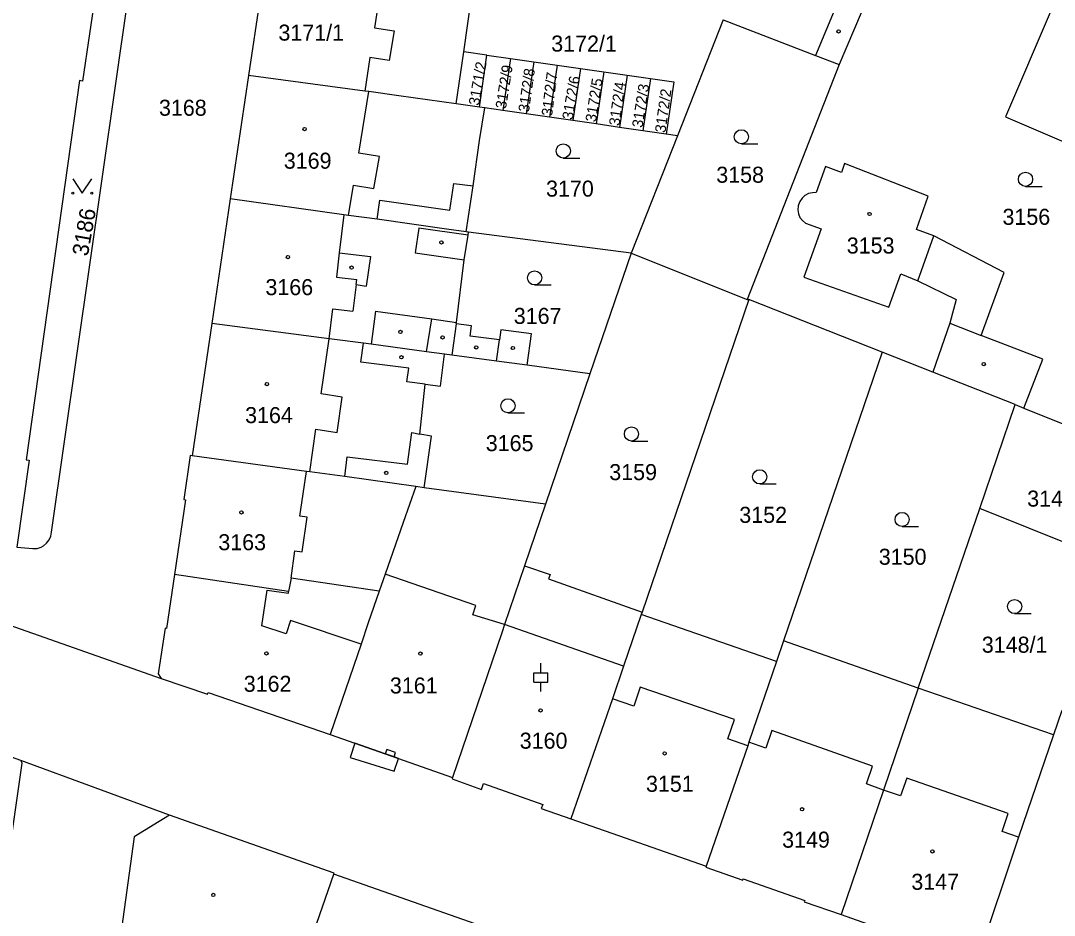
# Model space of a CAD drawing. Extents: x -756746 to -753363, y -1166406 to -1161727.
# Drawn here: x -755498.1 to -755388.6, y -1165398.7 to -1165303.9 of the extents above; entities that cross this region are included whole.
import ezdxf

# ---------------------------------------------------------------- set-up
doc = ezdxf.new("R2010")
doc.units = 0
for name, color, linetype in [('Hranice parcel', 7, 'Continuous'), ('Parcelní čísla', 7, 'Continuous'), ('Vnitřní kresba', 7, 'Continuous'), ('Věcná břemena k části', 7, 'Continuous'), ('Značky budov', 7, 'Continuous'), ('Značky kultur', 7, 'Continuous')]:
    doc.layers.add(name, color=color, linetype=linetype)

msp = doc.modelspace()

# ---------------------------------------------------------------- linework, layer by layer
at = {"layer": 'Hranice parcel'}
for p, q in [((-755471.99, -1165296.5), (-755474, -1165309.75)), ((-755451.19, -1165307.22), (-755450.11, -1165299.59)), ((-755494.86, -1165358.12), (-755486.67, -1165300.84)), ((-755423.7, -1165303.84), (-755428.53, -1165316.11)), ((-755451.98, -1165312.75), (-755451.19, -1165307.22)), ((-755448.72, -1165307.57), (-755451.19, -1165307.22)), ((-755449.5, -1165313.09), (-755448.72, -1165307.57)), ((-755448.72, -1165307.57), (-755446.24, -1165307.93)), ((-755446.24, -1165307.93), (-755447.03, -1165313.45)), ((-755446.24, -1165307.93), (-755443.77, -1165308.28)), ((-755443.77, -1165308.28), (-755444.56, -1165313.8)), ((-755443.77, -1165308.28), (-755441.29, -1165308.63)), ((-755441.29, -1165308.63), (-755442.08, -1165314.16)), ((-755441.29, -1165308.63), (-755438.82, -1165308.99)), ((-755438.82, -1165308.99), (-755439.61, -1165314.51)), ((-755438.82, -1165308.99), (-755436.35, -1165309.34)), ((-755436.35, -1165309.34), (-755437.14, -1165314.87)), ((-755436.35, -1165309.34), (-755433.87, -1165309.69)), ((-755411.4, -1165308.58), (-755421.15, -1165333.47)), ((-755474, -1165309.75), (-755475.94, -1165322.81)), ((-755433.87, -1165309.69), (-755434.66, -1165315.23)), ((-755433.87, -1165309.69), (-755431.4, -1165310.05)), ((-755431.4, -1165310.05), (-755432.19, -1165315.58)), ((-755449.5, -1165313.09), (-755451.98, -1165312.75)), ((-755448.94, -1165313.17), (-755449.5, -1165313.09)), ((-755447.03, -1165313.45), (-755448.94, -1165313.17)), ((-755444.56, -1165313.8), (-755447.03, -1165313.45)), ((-755442.08, -1165314.16), (-755444.56, -1165313.8)), ((-755439.61, -1165314.51), (-755442.08, -1165314.16)), ((-755437.14, -1165314.87), (-755439.61, -1165314.51)), ((-755434.66, -1165315.23), (-755437.14, -1165314.87)), ((-755432.19, -1165315.58), (-755434.66, -1165315.23)), ((-755429.72, -1165315.94), (-755432.19, -1165315.58)), ((-755428.53, -1165316.11), (-755429.72, -1165315.94)), ((-755428.53, -1165316.11), (-755433.43, -1165328.55)), ((-755475.94, -1165322.81), (-755477.87, -1165336.02)), ((-755450.68, -1165326.33), (-755450.94, -1165326.3)), ((-755433.43, -1165328.55), (-755450.68, -1165326.33)), ((-755433.43, -1165328.55), (-755437.82, -1165341.34)), ((-755433.43, -1165328.55), (-755421.15, -1165333.47)), ((-755420.97, -1165333.47), (-755432.28, -1165366.59)), ((-755421.15, -1165333.47), (-755420.97, -1165333.47)), ((-755406.85, -1165339.04), (-755420.97, -1165333.47)), ((-755477.87, -1165336.02), (-755479.96, -1165350.04)), ((-755406.85, -1165339.04), (-755417.29, -1165369.63)), ((-755401.46, -1165341.17), (-755406.85, -1165339.04)), ((-755437.82, -1165341.34), (-755444.46, -1165340.44)), ((-755437.82, -1165341.34), (-755442.52, -1165355.16)), ((-755392.74, -1165344.61), (-755401.46, -1165341.17)), ((-755396.5, -1165355.6), (-755392.74, -1165344.61)), ((-755392.74, -1165344.61), (-755391.83, -1165344.98)), ((-755391.83, -1165344.98), (-755382.11, -1165348.91)), ((-755455.36, -1165353.41), (-755456.26, -1165353.29)), ((-755442.52, -1165355.16), (-755455.36, -1165353.41)), ((-755442.52, -1165355.16), (-755444.74, -1165361.7)), ((-755403.01, -1165374.65), (-755396.5, -1165355.6)), ((-755382.39, -1165361.3), (-755396.5, -1165355.6)), ((-755498.54, -1165359.72), (-755496.83, -1165359.87)), ((-755506.24, -1165365.55), (-755483.26, -1165373.63)), ((-755432.28, -1165366.59), (-755432.37, -1165366.86)), ((-755418.04, -1165371.83), (-755432.37, -1165366.86)), ((-755417.29, -1165369.63), (-755418.04, -1165371.83)), ((-755403.01, -1165374.65), (-755417.29, -1165369.63)), ((-755388.69, -1165379.61), (-755403.01, -1165374.65)), ((-755498.12, -1165382.32), (-755517.96, -1165375.32)), ((-755387.8, -1165377.01), (-755388.69, -1165379.61)), ((-755465.33, -1165379.58), (-755452.36, -1165384.11)), ((-755482.36, -1165388.11), (-755498.12, -1165382.32)), ((-755439.84, -1165388.49), (-755425.48, -1165393.52)), ((-755449.97, -1165399.63), (-755464.94, -1165394.35))]:
    msp.add_line(p, q, dxfattribs=at)
for points in [[(-755400.67, -1165283.05), (-755405.9, -1165295.53), (-755409.08, -1165303.08), (-755411.4, -1165308.58)], [(-755383.67, -1165290.22), (-755388.84, -1165302.58), (-755393.78, -1165314.13), (-755381.65, -1165319.31)], [(-755490.09, -1165300.26), (-755491.58, -1165310.32), (-755491.89, -1165310.28), (-755497.54, -1165350.45), (-755497.25, -1165350.49), (-755498.54, -1165359.72)], [(-755423.7, -1165303.84), (-755413.92, -1165307.61), (-755411.4, -1165308.58)], [(-755451.98, -1165312.75), (-755458.05, -1165311.9), (-755461.23, -1165311.44), (-755461.68, -1165311.38), (-755474, -1165309.75)], [(-755431.4, -1165310.05), (-755428.93, -1165310.4), (-755429.72, -1165315.94)], [(-755450.94, -1165326.3), (-755450.19, -1165321.41), (-755449.51, -1165316.61), (-755448.94, -1165313.17)], [(-755391.83, -1165344.98), (-755389.81, -1165339.8), (-755396.35, -1165337.27), (-755393.92, -1165330.6), (-755401.37, -1165326.72), (-755403.22, -1165326.07), (-755401.96, -1165322.53), (-755410.82, -1165319.07), (-755411.16, -1165320.02), (-755412.83, -1165319.38), (-755413.82, -1165322.14)], [(-755413.82, -1165322.14), (-755414.24, -1165322.15), (-755414.65, -1165322.25), (-755415.02, -1165322.45), (-755415.33, -1165322.74), (-755415.57, -1165323.08), (-755415.6, -1165323.14), (-755415.73, -1165323.54), (-755415.77, -1165323.96), (-755415.71, -1165324.38), (-755415.55, -1165324.77), (-755415.3, -1165325.11), (-755414.98, -1165325.38)], [(-755450.94, -1165326.3), (-755453, -1165326.02), (-755460.36, -1165324.97), (-755463.39, -1165324.56), (-755463.89, -1165324.49), (-755475.94, -1165322.81)], [(-755414.98, -1165325.38), (-755413.3, -1165325.98), (-755415.13, -1165331.1), (-755406.14, -1165334.29), (-755404.88, -1165330.76), (-755403.05, -1165331.49), (-755398.99, -1165333.48), (-755399.67, -1165335.99), (-755401.46, -1165341.17)], [(-755444.46, -1165340.44), (-755444, -1165337.11), (-755447.26, -1165336.68), (-755447.41, -1165337.75), (-755450.5, -1165337.34), (-755450.36, -1165336.25), (-755451.97, -1165336.04), (-755451.95, -1165335.89), (-755451.14, -1165329.28), (-755450.73, -1165326.66), (-755450.68, -1165326.33)], [(-755453.21, -1165339.26), (-755455.13, -1165339), (-755460.99, -1165338.21), (-755461.81, -1165338.1), (-755465.44, -1165337.65), (-755477.87, -1165336.02)], [(-755455.36, -1165353.41), (-755454.6, -1165347.97), (-755455.85, -1165347.73), (-755455.28, -1165342.44), (-755453.64, -1165342.66), (-755453.21, -1165339.26)], [(-755444.46, -1165340.44), (-755447.72, -1165340), (-755452.46, -1165339.36), (-755453.21, -1165339.26)], [(-755479.96, -1165350.04), (-755480.16, -1165350.01), (-755480.84, -1165354.68), (-755480.67, -1165354.7), (-755481.84, -1165362.61)], [(-755456.26, -1165353.29), (-755463.8, -1165352.24), (-755467.5, -1165351.73), (-755467.83, -1165351.69), (-755479.96, -1165350.04)], [(-755456.26, -1165353.29), (-755457.6, -1165357.1), (-755459.51, -1165362.57), (-755460.14, -1165364.38)], [(-755496.83, -1165359.87), (-755496.4, -1165359.84), (-755495.98, -1165359.7), (-755495.73, -1165359.57), (-755495.39, -1165359.29), (-755495.12, -1165358.95), (-755494.95, -1165358.55), (-755494.86, -1165358.12)], [(-755444.74, -1165361.7), (-755446.86, -1165367.92), (-755447.15, -1165368.8), (-755452.36, -1165384.11)], [(-755444.74, -1165361.7), (-755442.04, -1165362.61), (-755442.19, -1165363.06), (-755432.28, -1165366.59)], [(-755481.84, -1165362.61), (-755482.67, -1165368.32), (-755482.84, -1165368.29), (-755483.55, -1165373.13), (-755483.26, -1165373.63)], [(-755460.14, -1165364.38), (-755469.48, -1165363), (-755469.74, -1165364.42), (-755481.84, -1165362.61)], [(-755460.14, -1165364.38), (-755461.31, -1165367.73), (-755462.07, -1165369.99), (-755465.33, -1165379.58)], [(-755432.37, -1165366.86), (-755434.24, -1165372.33), (-755435.43, -1165375.77), (-755439.84, -1165388.49)], [(-755418.04, -1165371.83), (-755420.96, -1165380.39), (-755421.09, -1165380.77), (-755425.48, -1165393.52)], [(-755483.26, -1165373.63), (-755478.32, -1165375.29), (-755478.26, -1165375.1), (-755465.33, -1165379.58)], [(-755403.01, -1165374.65), (-755406.7, -1165385.45), (-755411.19, -1165398.64)], [(-755388.69, -1165379.61), (-755392.39, -1165390.44), (-755396.79, -1165403.54)], [(-755500.08, -1165397.39), (-755497.96, -1165382.6), (-755498.12, -1165382.32)], [(-755452.36, -1165384.11), (-755452.42, -1165384.28), (-755449.31, -1165385.38), (-755449.09, -1165384.75), (-755442.81, -1165386.97), (-755442.96, -1165387.41), (-755439.84, -1165388.49)], [(-755482.36, -1165388.11), (-755486.1, -1165390.42), (-755488.63, -1165408.63)], [(-755464.94, -1165394.35), (-755464.9, -1165394.26), (-755482.36, -1165388.11)], [(-755425.48, -1165393.52), (-755425.52, -1165393.64), (-755421.62, -1165395), (-755421.57, -1165394.86), (-755415.04, -1165397.14), (-755415.09, -1165397.28), (-755411.19, -1165398.64)], [(-755470.69, -1165410.93), (-755468.93, -1165405.85), (-755468.82, -1165405.55), (-755464.94, -1165394.35)], [(-755411.19, -1165398.64), (-755407.3, -1165400.01), (-755407.24, -1165399.85), (-755400.69, -1165402.15), (-755400.75, -1165402.31), (-755396.84, -1165403.69), (-755396.79, -1165403.54)]]:
    msp.add_lwpolyline(points, dxfattribs=at)
at = {"layer": 'Vnitřní kresba'}
for p, q in [((-755459.67, -1165298.27), (-755460.65, -1165304.67)), ((-755411.58, -1165302.03), (-755413.92, -1165307.61)), ((-755460.65, -1165304.67), (-755458.56, -1165304.99)), ((-755458.56, -1165304.99), (-755459.07, -1165308.14)), ((-755461.13, -1165307.82), (-755461.68, -1165311.38)), ((-755459.07, -1165308.14), (-755461.13, -1165307.82)), ((-755462.31, -1165317.96), (-755461.23, -1165311.44)), ((-755460.11, -1165318.33), (-755462.31, -1165317.96)), ((-755460.7, -1165321.7), (-755460.11, -1165318.33)), ((-755463.39, -1165324.56), (-755462.86, -1165321.35)), ((-755462.86, -1165321.35), (-755460.7, -1165321.7)), ((-755452.64, -1165324.01), (-755452.25, -1165321.17)), ((-755452.25, -1165321.17), (-755450.19, -1165321.41)), ((-755460.36, -1165324.97), (-755460.08, -1165322.94)), ((-755460.08, -1165322.94), (-755452.64, -1165324.01)), ((-755463.89, -1165324.49), (-755464.37, -1165328.53)), ((-755455.93, -1165325.9), (-755456.32, -1165328.52)), ((-755450.73, -1165326.66), (-755455.93, -1165325.9)), ((-755403.05, -1165331.49), (-755401.37, -1165326.72)), ((-755464.37, -1165328.53), (-755464.67, -1165331.1)), ((-755464.37, -1165328.53), (-755461.08, -1165328.92)), ((-755461.08, -1165328.92), (-755461.51, -1165332.04)), ((-755456.32, -1165328.52), (-755451.14, -1165329.28)), ((-755464.67, -1165331.1), (-755462.51, -1165331.36)), ((-755462.57, -1165331.88), (-755462.92, -1165334.7)), ((-755462.57, -1165331.88), (-755462.51, -1165331.36)), ((-755462.57, -1165331.88), (-755461.51, -1165332.04)), ((-755465.44, -1165337.65), (-755465.06, -1165334.45)), ((-755465.06, -1165334.45), (-755462.92, -1165334.7)), ((-755460.53, -1165334.69), (-755460.99, -1165338.21)), ((-755460.53, -1165334.69), (-755454.58, -1165335.53)), ((-755455.13, -1165339), (-755454.58, -1165335.53)), ((-755454.58, -1165335.53), (-755451.95, -1165335.89)), ((-755451.97, -1165336.04), (-755452.46, -1165339.36)), ((-755399.67, -1165335.99), (-755396.35, -1165337.27)), ((-755466.29, -1165343.48), (-755465.44, -1165337.65)), ((-755447.72, -1165340), (-755447.41, -1165337.75)), ((-755462.09, -1165340.1), (-755461.81, -1165338.1)), ((-755457, -1165340.73), (-755462.09, -1165340.1)), ((-755457.2, -1165342.19), (-755457, -1165340.73)), ((-755455.28, -1165342.44), (-755457.2, -1165342.19)), ((-755464.05, -1165343.81), (-755466.29, -1165343.48)), ((-755464.6, -1165347.55), (-755464.05, -1165343.81)), ((-755467.5, -1165351.73), (-755466.84, -1165347.22)), ((-755466.84, -1165347.22), (-755464.6, -1165347.55)), ((-755457.14, -1165350.91), (-755456.68, -1165347.58)), ((-755456.68, -1165347.58), (-755455.85, -1165347.73)), ((-755463.8, -1165352.24), (-755463.55, -1165350.13)), ((-755463.55, -1165350.13), (-755457.14, -1165350.91)), ((-755468.54, -1165356.43), (-755467.83, -1165351.69)), ((-755467.76, -1165356.55), (-755468.54, -1165356.43)), ((-755468.31, -1165360.21), (-755467.76, -1165356.55)), ((-755469.48, -1165363), (-755469.09, -1165360.09)), ((-755469.09, -1165360.09), (-755468.31, -1165360.21)), ((-755449.9, -1165365.91), (-755459.51, -1165362.57)), ((-755472.57, -1165368.05), (-755472, -1165364.26)), ((-755472, -1165364.26), (-755469.77, -1165364.59)), ((-755469.77, -1165364.59), (-755469.74, -1165364.42)), ((-755450.23, -1165366.89), (-755449.9, -1165365.91)), ((-755446.86, -1165367.92), (-755450.23, -1165366.89)), ((-755470.01, -1165368.91), (-755472.57, -1165368.05)), ((-755469.53, -1165367.5), (-755470.01, -1165368.91)), ((-755462.07, -1165369.99), (-755469.53, -1165367.5)), ((-755434.24, -1165372.33), (-755446.86, -1165367.92)), ((-755432.47, -1165374.55), (-755433.16, -1165376.56)), ((-755422.48, -1165377.98), (-755432.47, -1165374.55)), ((-755433.16, -1165376.56), (-755435.43, -1165375.77)), ((-755423.18, -1165380.04), (-755422.48, -1165377.98)), ((-755418.52, -1165379.15), (-755419.18, -1165381.02)), ((-755407.86, -1165382.91), (-755418.52, -1165379.15)), ((-755421.09, -1165380.77), (-755423.18, -1165380.04)), ((-755419.18, -1165381.02), (-755420.96, -1165380.39)), ((-755408.51, -1165384.81), (-755407.86, -1165382.91)), ((-755406.7, -1165385.45), (-755408.51, -1165384.81)), ((-755404.22, -1165384.19), (-755404.9, -1165386.08)), ((-755393.48, -1165387.95), (-755404.22, -1165384.19)), ((-755404.9, -1165386.08), (-755406.7, -1165385.45)), ((-755394.14, -1165389.83), (-755393.48, -1165387.95)), ((-755392.39, -1165390.44), (-755394.14, -1165389.83))]:
    msp.add_line(p, q, dxfattribs=at)
at = {"layer": 'Věcná břemena k části'}
for points in [[(-755458.57, -1165381.94), (-755459.52, -1165381.61), (-755462.74, -1165380.48), (-755463.21, -1165381.99), (-755458.55, -1165383.46), (-755458.1, -1165382.1)], [(-755458.41, -1165381.47), (-755459.35, -1165381.14), (-755459.52, -1165381.61), (-755458.57, -1165381.94)]]:
    msp.add_lwpolyline(points, close=True, dxfattribs=at)
at = {"layer": 'Značky budov'}
for centre in [(-755411.46, -1165305.07), (-755468.05, -1165315.41), (-755408.18, -1165324.41), (-755453.54, -1165327.43), (-755469.81, -1165328.98), (-755463.07, -1165330.09), (-755457.9, -1165336.9), (-755453.43, -1165337.49), (-755449.86, -1165338.55), (-755445.98, -1165338.61), (-755457.79, -1165339.59), (-755396.08, -1165340.32), (-755472.04, -1165342.43), (-755459.39, -1165351.85), (-755474.75, -1165356.04), (-755472.09, -1165370.97), (-755455.77, -1165370.99), (-755443.04, -1165377.02), (-755429.89, -1165381.57), (-755415.33, -1165387.49), (-755401.52, -1165391.96), (-755477.72, -1165396.57)]:
    msp.add_circle(centre, 0.175, dxfattribs=at)
at = {"layer": 'Značky kultur'}
for p, q in [((-755421.76, -1165316.98), (-755420.01, -1165316.98)), ((-755440.63, -1165318.48), (-755438.88, -1165318.48)), ((-755391.65, -1165321.48), (-755389.9, -1165321.48)), ((-755443.67, -1165331.93), (-755441.92, -1165331.93)), ((-755446.5, -1165345.48), (-755444.75, -1165345.48)), ((-755433.41, -1165348.47), (-755431.66, -1165348.47)), ((-755419.82, -1165353.01), (-755418.07, -1165353.01)), ((-755404.73, -1165357.53), (-755402.98, -1165357.53)), ((-755392.8, -1165366.76), (-755391.05, -1165366.76)), ((-755443.02, -1165373.02), (-755443.02, -1165372.02)), ((-755443.77, -1165373.02), (-755442.27, -1165373.02)), ((-755443.77, -1165374.02), (-755443.77, -1165373.02)), ((-755442.27, -1165374.02), (-755442.27, -1165373.02)), ((-755443.77, -1165374.02), (-755442.27, -1165374.02)), ((-755443.02, -1165375.02), (-755443.02, -1165374.02))]:
    msp.add_line(p, q, dxfattribs=at)
msp.add_lwpolyline([(-755492.61, -1165320.7), (-755491.61, -1165322.2), (-755490.61, -1165320.7)], dxfattribs=at)
for centre, radius in [((-755421.76, -1165316.23), 0.75), ((-755440.63, -1165317.73), 0.75), ((-755391.65, -1165320.73), 0.75), ((-755492.61, -1165322.2), 0.1), ((-755490.61, -1165322.2), 0.1), ((-755443.67, -1165331.18), 0.75), ((-755446.5, -1165344.73), 0.75), ((-755433.41, -1165347.72), 0.75), ((-755419.82, -1165352.26), 0.75), ((-755404.73, -1165356.78), 0.75), ((-755392.8, -1165366.01), 0.75)]:
    msp.add_circle(centre, radius, dxfattribs=at)

# ---------------------------------------------------------------- texts
at = {"layer": 'Parcelní čísla'}
for s, p in [('3171/1', (-755470.82, -1165306.04)), ('3172/1', (-755441.91, -1165307.2)), ('3168', (-755483.48, -1165314)), ('3169', (-755470.25, -1165319.61)), ('3158', (-755424.42, -1165321.1)), ('3170', (-755442.46, -1165322.57)), ('3156', (-755394.09, -1165325.56)), ('3153', (-755410.59, -1165328.6)), ('3166', (-755472.2, -1165333.01)), ('3167', (-755445.88, -1165336.06)), ('3164', (-755474.35, -1165346.57)), ('3165', (-755448.85, -1165349.54)), ('3159', (-755435.76, -1165352.61)), ('3148/2', (-755391.47, -1165355.42)), ('3152', (-755421.98, -1165357.14)), ('3163', (-755477.19, -1165360.04)), ('3150', (-755407.2, -1165361.58)), ('3148/1', (-755396.28, -1165370.9)), ('3162', (-755474.5, -1165375.04)), ('3161', (-755459.01, -1165375.22)), ('3160', (-755445.25, -1165381.07)), ('3151', (-755431.87, -1165385.64)), ('3149', (-755417.44, -1165391.56)), ('3147', (-755403.75, -1165396.02))]:
    msp.add_text(s, height=1.7, dxfattribs=at).set_placement(p)
for s, height, rotation, p in [('3171/2', 1.139, 80, (-755449.56, -1165312.97)), ('3172/9', 1.139, 81, (-755446.71, -1165313.32)), ('3172/8', 1.139, 82, (-755444.28, -1165313.67)), ('3172/7', 1.139, 83, (-755441.82, -1165314.08)), ('3172/6', 1.139, 80, (-755439.65, -1165314.48)), ('3172/5', 1.139, 81, (-755437.18, -1165314.72)), ('3172/4', 1.139, 82, (-755434.68, -1165315.11)), ('3172/3', 1.139, 81, (-755432.24, -1165315.32)), ('3172/2', 1.139, 82, (-755429.81, -1165315.85)), ('3186', 1.7, 80, (-755491.02, -1165328.95))]:
    msp.add_text(s, height=height, rotation=rotation, dxfattribs=at).set_placement(p)

doc.saveas('drawing.dxf')
